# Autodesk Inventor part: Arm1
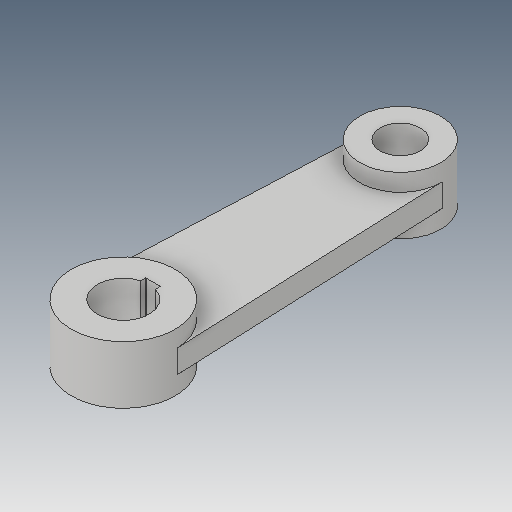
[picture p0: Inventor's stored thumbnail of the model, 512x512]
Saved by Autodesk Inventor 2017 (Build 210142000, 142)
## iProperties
Created: 2016-05
Part Number: Arm1
Material: Generic
Document SubType Name: Modeling
Designer: CADCIM
Density: 1 g/cm^3
Appearance: Default
Author: CADCIM
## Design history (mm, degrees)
sketch "Sketch1"
  geometry: C1 r 56.25 at (0, 0); C2 r 28 at (0, 0); C3 r 43.75 at (0, -300); C4 r 21.75 at (0, -300); 1 further point
  constraints: 4 centre point, 3 coincident
  dimensions: "d0" = 112.5 diameter of C1; "d1" = 56 diameter of C2; "d2" = 87.5 diameter of C3; "d3" = 43.5 diameter of C4; "d4" = 300 distance of C4.centre C2.centre
extrude "Extrusion1" new body sketch "Sketch1" stored distance "d5" = 62.5; taper "d6" = 0 deg
sketch "Sketch2"
  geometry: L1 (56.201, -2.344)-(43.712, -301.823); L2 (-56.201, -2.344)-(-43.712, -301.823); A1 r 56.25 centre (0, 0) between (-56.201, -2.344) and (56.201, -2.344); A2 r 43.75 centre (0, -300) between (43.712, -301.823) and (-43.712, -301.823); 3 further points
  constraints: 4 end point, 4 point on circle, 2 centre point, 2 coincident
extrude "Extrusion2" join sketch "Sketch2" stored distance "d7" = 25; taper "d8" = 0 deg
sketch "Sketch3"
  geometry: L1 (0, 0)-(0, 99.622); L2 (-8, 26.833)-(8, 26.833); L3 (8, 26.833)-(8, 32.3); L4 (8, 32.3)-(-8, 32.3); L5 (-8, 32.3)-(-8, 26.833); L6 (0, 0)-(0, -28); A1 r 28 centre (0, 0) between (-8, 26.833) and (8, 26.833) reference
  constraints: 12 end point, 3 point on circle, 2 parallel, 2 vertical, 1 horizontal, 1 perpendicular, 1 other
  dimensions: "d10" = 16 distance of L3.end L4.end; "d11" = 60.3 distance from line of L4 L6.end
extrude "Extrusion3" cut sketch "Sketch3" stored distance "d12" = 25; taper "d13" = 0 deg
fillet "Fillet1" dims "d14" = 0.4
body "Solid1"
